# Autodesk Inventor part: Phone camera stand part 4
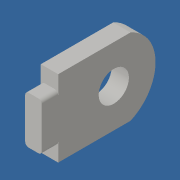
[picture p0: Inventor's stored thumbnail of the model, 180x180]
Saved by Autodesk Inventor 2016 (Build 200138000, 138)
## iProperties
Created: 2016-02
Part Number: Phone camera stand part 4
Material: Generic
Document SubType Name: Modeling
Designer: Miha
Density: 1 g/cm^3
Appearance: Default
Author: Miha
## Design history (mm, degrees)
sketch "Sketch1"
  geometry: L1 (0, 0)-(28, 0); L2 (28, 0)-(28, -22); L3 (28, -22)-(0, -22); L4 (0, -22)-(0, 0)
  constraints: 8 end point, 2 parallel, 1 horizontal, 1 perpendicular
  dimensions: "d0" = 28 distance of L2.end L3.end; "d1" = 22 distance of L1.end L2.end
extrude "Extrusion1" new body sketch "Sketch1" distance "d2" = 5; taper "d3" = 0 deg
sketch "Sketch2"
  geometry: L1 (0, 0)-(22, 0) reference; L2 (11, 0)-(27, 0); C1 r 4.35 at (11, 16)
  constraints: 2 end point, 1 centre point, 1 horizontal, 1 midpoint
  dimensions: "d6" = 8.7 diameter of C1
extrude "Extrusion2" cut sketch "Sketch2" distance "d7" = 5; taper "d8" = 0 deg
sketch "Sketch3"
  geometry: L1 (22, 28)-(22, 0) reference; L2 (22, 28)-(22, 0); L3 (0, 28)-(22, 28) reference; L4 (22, 28)-(0, 28); L5 (0, 0)-(0, 28) reference; L6 (0, 28)-(0, 0); C1 r 4.35 at (11, 16) reference; A1 r 12 centre (11, 16) between (22, 20.796) and (0, 20.796); A2 r 12 centre (11, 16) between (22, 20.796) and (0, 20.796)
  constraints: 6 end point, 4 point on circle, 2 centre point, 2 collinear, 2 point on line, 1 coincident, 1 horizontal
extrude "Extrusion3" cut sketch "Sketch3" distance "d9" = 5; taper "d10" = 0 deg
sketch "Sketch4"
  geometry: L1 (5, 15.35)-(5, 6.65) reference; L2 (0, 0)-(0, 22) reference; L3 (5, 11)-(2.6, 11); L4 (5, 11)-(7.4, 11); L5 (0.2, 17.825)-(5, 17.825); L6 (5, 17.825)-(5, 4.175); L7 (5, 4.175)-(0.2, 4.175); L8 (0.2, 4.175)-(0.2, 17.825); L9 (0.2, 17.825)-(5, 4.175); L10 (5, 17.825)-(0.2, 4.175)
  constraints: 16 end point, 3 midpoint, 2 horizontal, 2 parallel, 1 collinear, 1 perpendicular
  dimensions: "d13" = 2.4 distance of L3.start L3.end; "d14" = 180 deg angle of L3 L4 (derived); "d15" = 4.8 distance of L6.end L7.end; "d16" = 13.65 distance of L5.end L6.end
extrude "Extrusion4" join sketch "Sketch4" distance "d17" = 7; taper "d18" = 0 deg
fillet "Fillet1" dims "d19" = 1
sketch "Sketch6"
  geometry: L1 (5, 16.825)-(5, 22) reference; L2 (0, 0)-(5, 0); L3 (5, 0)-(5, 22); L4 (5, 22)-(0, 22); L5 (0, 22)-(0, 0); 1 further point
  constraints: 8 end point, 2 parallel, 1 horizontal, 1 perpendicular
extrude "Extrusion6" cut sketch "Sketch6" distance "d22" = 2.3; taper "d23" = 0 deg
body "Solid1"
